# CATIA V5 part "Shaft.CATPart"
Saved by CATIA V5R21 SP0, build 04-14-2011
Part number: Shaft
Bounding box of the stored display mesh (mm): x -10.997 to 10.997, y 0 to 134, z -10.875 to 10.875
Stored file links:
  D:\CATIA V5R21 E-RESOURCES\CATIA-V5R21\catia-v5r21-Prts\c12_catia_v5r21_prt\c12_catia_v5r21figr_12-49\Shaft.CATPart
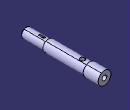
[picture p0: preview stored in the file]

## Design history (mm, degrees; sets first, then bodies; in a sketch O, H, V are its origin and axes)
Body1 (main body)
  Sketch1 on yz-plane, origin (0, 0, 0), H (0, 1, 0), V (0, 0, 1)
    line L1 (0, 0) -> (0, 8)
    line L2 (0, 8) -> (39, 8)
    line L3 (39, 8) -> (39, 9.5)
    line L4 (39, 9.5) -> (109, 9.5)
    line L5 (109, 9.5) -> (109, 11)
    line L6 (109, 11) -> (134, 11)
    line L7 (134, 11) -> (134, 0)
    point P7 (134, 0)
    line L8 (134, 0) -> (0, 0)
    length L1 = 8
    length L8 = 134
    length L7 = 11
    distance L4 L8 = 9.5
    length L6 = 25
    length L4 = 70
    vertical: L1 V, L3 V, L5 V, L7 V
    horizontal: L2 H, L4 H, L6 H, L8 H
    coincidence: P7 H
  Shaft1: profile Sketch1, axis edge of Sketch1, angle 360
  Chamfer1: length 1.5, angle 45, on 1 edge
  Sketch2 on xy-plane, origin (0, 0, 0), H (1, 0, 0), V (0, 1, 0)
    circle A1 centre (0, 97) radius 4.15
    point P1 (0, 97)
    reference projected line E1 (-11, 109) -> (11, 109) from edge of Shaft1
    radius A1 = 4.15
    distance E1 P1 = 12
    coincidence: P1 V
  Pocket1: profile Sketch2, direction (0, 0, -1), length 20, mirrored extent
  Sketch3 on face of Shaft1, origin (0, 134, 0), H (-1, 0, 0), V (0, 0, 1)
    circle A1 centre (0, 0) radius 4.15
    radius A1 = 4.15
  Pocket2: profile Sketch3, direction (0, -1, 0), length 44
  Sketch4 on yz-plane, origin (0, 0, 0), H (0, 1, 0), V (0, 0, 1)
    point P1 (23, 8)
    line L1 (23, 8) -> (33, 8)
    arc A1 centre (28, 12.899) radius 7 from (23, 8) to (33, 8) ccw
    reference projected line E1 (39, -9.5) -> (39, 9.5) from edge of Shaft1
    length L1 = 10
    distance L1 H = 8
    distance P1 E1 = 16
    radius A1 = 7
    horizontal: L1 H
  Pocket3: profile Sketch4, direction (-1, 0, 0), length 1.6, mirrored extent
